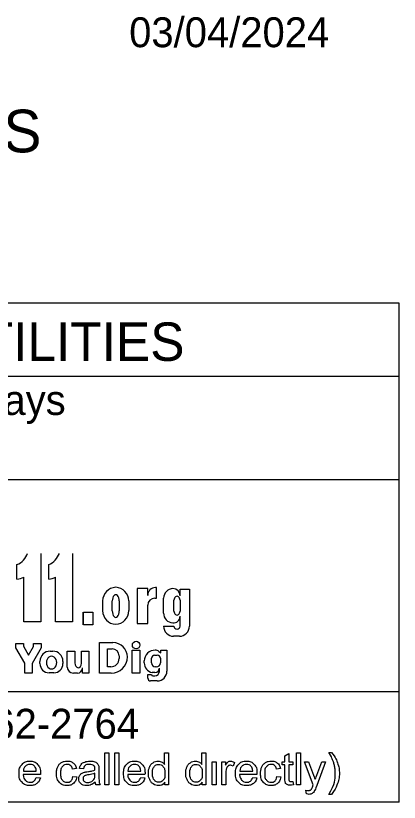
# Model space of a CAD drawing. Extents: x -3.3 to 34, y 0 to 56.8.
# Drawn here: x 4.831 to 6.628, y 1.905 to 5.59 of the extents above; entities that cross this region are included whole.
import ezdxf

# ---------------------------------------------------------------- set-up
doc = ezdxf.new("R2010")
doc.units = 0
doc.layers.add('SH_Data', color=7, linetype='Continuous')
doc.layers.add('SH_Major_Grid_Line', color=7, linetype='Continuous')

msp = doc.modelspace()

# ---------------------------------------------------------------- linework, layer by layer
at = {"layer": 'SH_Data'}
for p, q in [((6.6275, 4.2428), (2.3775, 4.2428)), ((6.6275, 1.9053), (6.6275, 4.2428)), ((2.3775, 3.9012), (6.6275, 3.9012)), ((2.3775, 3.4178), (6.6275, 3.4178)), ((6.6275, 2.4232), (2.3775, 2.4232)), ((6.6275, 1.9053), (2.3775, 1.9053))]:
    msp.add_line(p, q, dxfattribs=at)
at = {"layer": 'SH_Major_Grid_Line'}
for p, q in [((4.9487, 3.0712), (4.9487, 2.7512)), ((5.0975, 3.0712), (5.0975, 2.7512)), ((4.8371, 2.9505), (4.8371, 3.0187)), ((4.9859, 2.9505), (4.9859, 3.0187)), ((4.8694, 2.7512), (4.8694, 2.9598)), ((5.0182, 2.7512), (5.0182, 2.9598)), ((5.49, 2.9112), (5.486, 2.9112)), ((5.49, 2.8614), (5.49, 2.9112)), ((5.4493, 2.9061), (5.4005, 2.9061)), ((5.4005, 2.9061), (5.4005, 2.7431)), ((5.4493, 2.8745), (5.4493, 2.9061)), ((5.6009, 2.8719), (5.6009, 2.9029)), ((5.6009, 2.9029), (5.6444, 2.9029)), ((5.6444, 2.9029), (5.6444, 2.73)), ((5.2385, 2.8029), (5.2385, 2.8483)), ((5.2835, 2.8021), (5.2835, 2.8483)), ((5.3157, 2.8483), (5.3157, 2.8021)), ((5.3606, 2.8483), (5.3606, 2.8029)), ((5.4823, 2.8614), (5.49, 2.8614)), ((5.5239, 2.7915), (5.5239, 2.8611)), ((5.5723, 2.8008), (5.5723, 2.8518)), ((5.6009, 2.8518), (5.6009, 2.8008)), ((5.4493, 2.7431), (5.4493, 2.8284)), ((5.1456, 2.7962), (5.1456, 2.7362)), ((5.6009, 2.73), (5.6009, 2.7764)), ((4.9487, 2.7512), (4.8694, 2.7512)), ((5.0975, 2.7512), (5.0182, 2.7512)), ((5.4005, 2.7431), (5.4493, 2.7431)), ((5.5239, 2.73), (5.5723, 2.73)), ((5.2243, 2.6531), (5.2866, 2.6531)), ((5.2243, 2.5103), (5.2243, 2.6531)), ((5.5977, 2.6833), (5.5707, 2.6833)), ((4.8319, 2.6495), (4.8677, 2.6495)), ((4.8319, 2.628), (4.8319, 2.6495)), ((4.8732, 2.5571), (4.8319, 2.628)), ((4.8677, 2.6495), (4.8677, 2.6359)), ((4.8677, 2.6359), (4.8918, 2.5945)), ((4.8918, 2.5945), (4.9151, 2.6344)), ((4.9509, 2.628), (4.9088, 2.5557)), ((4.9151, 2.6344), (4.9151, 2.6495)), ((4.9151, 2.6495), (4.9509, 2.6495)), ((4.9509, 2.6495), (4.9509, 2.628)), ((5.2603, 2.5398), (5.2603, 2.6238)), ((5.2603, 2.6238), (5.2828, 2.6238)), ((5.377, 2.6174), (5.4126, 2.6174)), ((5.377, 2.5103), (5.377, 2.6174)), ((5.4126, 2.6174), (5.4126, 2.5103)), ((5.5107, 2.6178), (5.5395, 2.6178)), ((5.5107, 2.6052), (5.5107, 2.6178)), ((5.5107, 2.6178), (5.5395, 2.6178)), ((5.5395, 2.6178), (5.5395, 2.5192)), ((4.9925, 2.6133), (5.0047, 2.6133)), ((5.0727, 2.6133), (5.1075, 2.6133)), ((5.0727, 2.5387), (5.0727, 2.6133)), ((5.1075, 2.6133), (5.1075, 2.5579)), ((5.1388, 2.5563), (5.1388, 2.6133)), ((5.1388, 2.6133), (5.1736, 2.6133)), ((5.1736, 2.6133), (5.1736, 2.5103)), ((5.3154, 2.5911), (5.3154, 2.5793)), ((5.467, 2.5586), (5.467, 2.5798)), ((5.4816, 2.5944), (5.4944, 2.5944)), ((5.5021, 2.6118), (5.5107, 2.6052)), ((5.509, 2.5798), (5.509, 2.5586)), ((4.8732, 2.5103), (4.8732, 2.5571)), ((4.9088, 2.5557), (4.9088, 2.5103)), ((4.9447, 2.5547), (4.9447, 2.5654)), ((5.0525, 2.5654), (5.0525, 2.5547)), ((5.4335, 2.5578), (5.4335, 2.5679)), ((4.9088, 2.5103), (4.8732, 2.5103)), ((5.0097, 2.5119), (4.9875, 2.5119)), ((5.1199, 2.5103), (5.1011, 2.5103)), ((5.1439, 2.5103), (5.1439, 2.5344)), ((5.1736, 2.5103), (5.1439, 2.5103)), ((5.2779, 2.5103), (5.2243, 2.5103)), ((5.2759, 2.5398), (5.2603, 2.5398)), ((5.4126, 2.5103), (5.377, 2.5103)), ((5.4835, 2.5131), (5.4698, 2.5131)), ((5.4897, 2.5393), (5.4863, 2.5393)), ((5.5039, 2.5182), (5.5039, 2.5336)), ((5.45, 2.487), (5.45, 2.504)), ((5.45, 2.504), (5.467, 2.504)), ((5.4942, 2.4739), (5.4631, 2.4739)), ((5.4738, 2.497), (5.4827, 2.497))]:
    msp.add_line(p, q, dxfattribs=at)
msp.add_lwpolyline([(5.148, 2.7962), (5.1921, 2.7962), (5.1921, 2.7362), (5.148, 2.7362)], close=True, dxfattribs=at)
for points in [[(6.2974, 2.1391), (6.3105, 2.1391)], [(5.2491, 1.9864), (5.2491, 2.1366), (5.2675, 2.1366), (5.2675, 1.9864), (5.2491, 1.9864)], [(5.2956, 1.9864), (5.2956, 2.1366), (5.3141, 2.1366), (5.3141, 1.9864), (5.2956, 1.9864)], [(5.5285, 2.0827), (5.5285, 2.1366), (5.5469, 2.1366), (5.5469, 1.9864), (5.5299, 1.9864)], [(5.7034, 2.0827), (5.7034, 2.1366), (5.7218, 2.1366), (5.7218, 1.9864), (5.7048, 1.9864)], [(6.092, 2.0183), (6.092, 2.081), (6.0784, 2.081), (6.0784, 2.0953), (6.092, 2.0953), (6.092, 2.1222), (6.1105, 2.1333), (6.1105, 2.0953), (6.1289, 2.0953), (6.1289, 2.081), (6.1105, 2.081), (6.1105, 2.0172)], [(6.1465, 1.9864), (6.1465, 2.1366), (6.1649, 2.1366), (6.1649, 1.9864), (6.1465, 1.9864)], [(5.1479, 2.0617), (5.1298, 2.0641)], [(5.7509, 1.9864), (5.7509, 2.0953), (5.7693, 2.0953), (5.7693, 1.9864), (5.7509, 1.9864)], [(5.7971, 1.9864), (5.7971, 2.0953), (5.8137, 2.0953), (5.8137, 2.0788)], [(5.8562, 2.0918), (5.8497, 2.0747)], [(6.2243, 1.9863), (6.183, 2.0953), (6.2029, 2.0953), (6.2255, 2.0324)], [(6.241, 2.0318), (6.2643, 2.0953), (6.2827, 2.0953), (6.2414, 1.9845)], [(4.947, 2.0361), (4.8659, 2.0361)], [(4.8669, 2.0512), (4.9277, 2.0512)], [(5.1154, 2.0632), (5.0974, 2.0605)], [(5.2023, 2.0343), (5.2024, 2.041)], [(5.2209, 2.0566), (5.2209, 2.032)], [(5.4366, 2.0361), (5.3555, 2.0361)], [(5.3565, 2.0512), (5.4173, 2.0512)], [(5.8155, 2.0434), (5.8155, 1.9864), (5.7971, 1.9864)], [(5.9611, 2.0361), (5.88, 2.0361)], [(5.881, 2.0512), (5.9418, 2.0512)], [(6.0712, 2.0632), (6.0532, 2.0605)], [(4.9275, 2.0216), (4.9465, 2.0192)], [(5.099, 2.0263), (5.1171, 2.0238)], [(5.4171, 2.0216), (5.4361, 2.0192)], [(5.5299, 1.9864), (5.5299, 2.0001)], [(5.7048, 1.9864), (5.7048, 2.0001)], [(5.9416, 2.0216), (5.9606, 2.0192)], [(6.0548, 2.0263), (6.0729, 2.0238)], [(6.1289, 2.0029), (6.1315, 1.9866)], [(5.2267, 1.9864), (5.2075, 1.9864)], [(6.1928, 1.9446), (6.1907, 1.962)], [(6.3105, 1.9422), (6.2974, 1.9422)]]:
    msp.add_lwpolyline(points, dxfattribs=at)
msp.add_circle((5.3952, 2.6418), 0.0177, dxfattribs=at)
for centre, radius, start, end in [((4.8031, 3.1004), 0.0885, 292.5572, 340.7355), ((4.952, 3.1004), 0.0885, 292.5572, 340.7355), ((4.8291, 3.0386), 0.0885, 275.1733, 297.0931), ((4.9779, 3.0386), 0.0885, 275.1733, 297.0931), ((5.3024, 2.8483), 0.064, 92.5886, 180), ((5.2967, 2.8483), 0.064, 0, 87.4114), ((5.486, 2.8745), 0.0367, 90, 180), ((5.5698, 2.8611), 0.0459, 92.6865, 180), ((5.5658, 2.8719), 0.0351, 0, 86.9262), ((5.4823, 2.8284), 0.033, 90, 180), ((5.3024, 2.8029), 0.064, 180, 267.4114), ((5.2967, 2.8029), 0.064, 272.5886, 0), ((5.5702, 2.7915), 0.0463, 180, 265.7132), ((5.5696, 2.7764), 0.0313, 264.7825, 0), ((5.5707, 2.73), 0.0468, 180, 270), ((5.5977, 2.73), 0.0468, 270, 0), ((5.2866, 2.5848), 0.0682, 0.9944, 90), ((5.2828, 2.5911), 0.0327, 0, 90), ((5.4834, 2.5679), 0.0499, 89.0934, 180), ((5.4848, 2.5895), 0.0283, 52.1415, 91.2046), ((4.9925, 2.5654), 0.0478, 90, 180), ((5.0047, 2.5654), 0.0478, 0, 90), ((5.2779, 2.5873), 0.0769, 270, 359.0635), ((5.4816, 2.5798), 0.0146, 90, 180), ((5.4944, 2.5798), 0.0146, 0, 90), ((4.9875, 2.5547), 0.0428, 180, 270), ((5.0097, 2.5547), 0.0428, 270, 0), ((5.2759, 2.5793), 0.0395, 270, 0), ((5.4791, 2.5578), 0.0457, 180, 258.2203), ((5.4863, 2.5586), 0.0193, 180, 270), ((5.4897, 2.5586), 0.0193, 270, 0), ((5.1011, 2.5387), 0.0284, 180, 270), ((5.1199, 2.5344), 0.024, 270, 0), ((5.4827, 2.5182), 0.0212, 270, 0), ((5.4835, 2.5335), 0.0203, 270, 0), ((5.4942, 2.5192), 0.0453, 270, 0), ((5.4631, 2.487), 0.0131, 180, 270), ((5.4738, 2.5038), 0.00682, 180, 270)]:
    msp.add_arc(centre, radius, start, end, dxfattribs=at)
for centre, major_axis, ratio, start_param, end_param in [((5.2996, 2.8483), (0, 0.0291), 0.553236, 4.712389, 7.853982), ((5.5866, 2.8518), (0, 0.0184), 0.777179, 4.712389, 7.853982), ((5.2996, 2.8021), (0, 0.0308), 0.522014, 1.570796, 4.712389), ((5.5866, 2.8008), (0, 0.0184), 0.777179, 1.570796, 4.712389), ((5.5866, 2.73), (0.0143, 0), 0.959012, 3.141593, 6.283185), ((4.9991, 2.5601), (0, 0.029), 0.832186, 4.712389, 7.853982), ((4.9991, 2.5601), (0, 0.0302), 0.797287, 1.570796, 4.712389), ((5.1231, 2.5587), (-0.0011, 0.0231), 0.679042, 1.570796, 4.575961)]:
    msp.add_ellipse(centre, major_axis=major_axis, ratio=ratio, start_param=start_param, end_param=end_param, dxfattribs=at)
for points, degree in [([(6.2974, 1.9422), (6.3279, 1.9914), (6.3279, 2.0407), (6.3279, 2.0599), (6.3235, 2.0789), (6.32, 2.0942), (6.3138, 2.1084), (6.3098, 2.1176), (6.2974, 2.1391)], 3), ([(6.3105, 2.1391), (6.3298, 2.1134), (6.339, 2.0875), (6.3469, 2.0651), (6.3469, 2.0408), (6.3469, 2.0131), (6.3363, 1.9873), (6.3257, 1.9615), (6.3105, 1.9422)], 3), ([(4.9465, 2.0192), (4.942, 2.0025), (4.9298, 1.9932), (4.9177, 1.984), (4.8987, 1.984), (4.8749, 1.984), (4.8609, 1.9987), (4.8469, 2.0134), (4.8469, 2.0399), (4.8469, 2.0674), (4.861, 2.0825), (4.8752, 2.0977), (4.8977, 2.0977), (4.9195, 2.0977), (4.9333, 2.0828), (4.9471, 2.068), (4.9471, 2.041), (4.9471, 2.0394), (4.947, 2.0361)], 3), ([(4.9277, 2.0512), (4.9265, 2.065), (4.9207, 2.0719), (4.9119, 2.0826), (4.8979, 2.0826), (4.8852, 2.0826), (4.8765, 2.074), (4.8678, 2.0655), (4.8669, 2.0512)], 3), ([(5.1171, 2.0238), (5.1141, 2.0052), (5.1019, 1.9946), (5.0896, 1.984), (5.0718, 1.984), (5.0495, 1.984), (5.0359, 1.9986), (5.0223, 2.0132), (5.0223, 2.0404), (5.0223, 2.058), (5.0282, 2.0712), (5.034, 2.0845), (5.046, 2.0911), (5.0579, 2.0977), (5.0719, 2.0977), (5.0897, 2.0977), (5.1009, 2.0887), (5.1122, 2.0797), (5.1154, 2.0632)], 3), ([(5.0974, 2.0605), (5.0949, 2.0715), (5.0884, 2.077), (5.0819, 2.0826), (5.0726, 2.0826), (5.0587, 2.0826), (5.05, 2.0726), (5.0413, 2.0626), (5.0413, 2.0409), (5.0413, 2.019), (5.0497, 2.0091), (5.0581, 1.9991), (5.0717, 1.9991), (5.0825, 1.9991), (5.0898, 2.0058), (5.0971, 2.0124), (5.099, 2.0263)], 3), ([(5.2038, 1.9998), (5.1936, 1.9912), (5.1841, 1.9876), (5.1746, 1.984), (5.1638, 1.984), (5.1458, 1.984), (5.1362, 1.9928), (5.1266, 2.0015), (5.1266, 2.0151), (5.1266, 2.0231), (5.1302, 2.0297), (5.1339, 2.0363), (5.1398, 2.0403), (5.1456, 2.0443), (5.153, 2.0463), (5.1584, 2.0478), (5.1694, 2.0491), (5.1917, 2.0518), (5.2023, 2.0554), (5.2024, 2.0592), (5.2024, 2.0603), (5.2024, 2.0716), (5.1971, 2.0762), (5.1901, 2.0824), (5.1762, 2.0824), (5.1632, 2.0824), (5.157, 2.0779), (5.1508, 2.0733), (5.1479, 2.0617)], 3), ([(5.1298, 2.0641), (5.1323, 2.0757), (5.1379, 2.0828), (5.1435, 2.09), (5.1542, 2.0938), (5.1648, 2.0977), (5.1788, 2.0977), (5.1928, 2.0977), (5.2015, 2.0944), (5.2102, 2.0911), (5.2142, 2.0861), (5.2183, 2.0812), (5.22, 2.0736), (5.2209, 2.0689), (5.2209, 2.0566)], 3), ([(5.4361, 2.0192), (5.4316, 2.0025), (5.4194, 1.9932), (5.4072, 1.984), (5.3883, 1.984), (5.3644, 1.984), (5.3505, 1.9987), (5.3365, 2.0134), (5.3365, 2.0399), (5.3365, 2.0674), (5.3506, 2.0825), (5.3648, 2.0977), (5.3873, 2.0977), (5.4091, 2.0977), (5.4229, 2.0828), (5.4367, 2.068), (5.4367, 2.041), (5.4367, 2.0394), (5.4366, 2.0361)], 3), ([(5.4173, 2.0512), (5.4161, 2.065), (5.4103, 2.0719), (5.4015, 2.0826), (5.3875, 2.0826), (5.3748, 2.0826), (5.3661, 2.074), (5.3574, 2.0655), (5.3565, 2.0512)], 3), ([(5.5299, 2.0001), (5.5195, 1.984), (5.4995, 1.984), (5.4865, 1.984), (5.4755, 1.9912), (5.4646, 1.9984), (5.4586, 2.0112), (5.4526, 2.0241), (5.4526, 2.0407), (5.4526, 2.057), (5.4581, 2.0703), (5.4635, 2.0835), (5.4743, 2.0906), (5.4852, 2.0977), (5.4986, 2.0977), (5.5084, 2.0977), (5.516, 2.0935), (5.5237, 2.0894), (5.5285, 2.0827)], 3), ([(5.4716, 2.0407), (5.4716, 2.0198), (5.4805, 2.0095), (5.4893, 1.9991), (5.5012, 1.9991), (5.5133, 1.9991), (5.5218, 2.009), (5.5302, 2.0189), (5.5302, 2.0392), (5.5302, 2.0615), (5.5216, 2.072), (5.513, 2.0824), (5.5004, 2.0824), (5.4881, 2.0824), (5.4799, 2.0724), (5.4716, 2.0624), (5.4716, 2.0407)], 3), ([(5.7048, 2.0001), (5.6944, 1.984), (5.6743, 1.984), (5.6613, 1.984), (5.6504, 1.9912), (5.6395, 1.9984), (5.6335, 2.0112), (5.6275, 2.0241), (5.6275, 2.0407), (5.6275, 2.057), (5.6329, 2.0703), (5.6384, 2.0835), (5.6492, 2.0906), (5.66, 2.0977), (5.6734, 2.0977), (5.6832, 2.0977), (5.6909, 2.0935), (5.6986, 2.0894), (5.7034, 2.0827)], 3), ([(5.6465, 2.0407), (5.6465, 2.0198), (5.6553, 2.0095), (5.6641, 1.9991), (5.6761, 1.9991), (5.6882, 1.9991), (5.6967, 2.009), (5.7051, 2.0189), (5.7051, 2.0392), (5.7051, 2.0615), (5.6965, 2.072), (5.6879, 2.0824), (5.6753, 2.0824), (5.663, 2.0824), (5.6548, 2.0724), (5.6465, 2.0624), (5.6465, 2.0407)], 3), ([(5.8137, 2.0788), (5.8201, 2.0903), (5.8254, 2.094), (5.8308, 2.0977), (5.8372, 2.0977), (5.8466, 2.0977), (5.8562, 2.0918)], 3), ([(5.8497, 2.0747), (5.843, 2.0787), (5.8363, 2.0787), (5.8302, 2.0787), (5.8255, 2.075), (5.8207, 2.0714), (5.8186, 2.0649), (5.8155, 2.0551), (5.8155, 2.0434)], 3), ([(5.9606, 2.0192), (5.9561, 2.0025), (5.9439, 1.9932), (5.9317, 1.984), (5.9128, 1.984), (5.8889, 1.984), (5.875, 1.9987), (5.861, 2.0134), (5.861, 2.0399), (5.861, 2.0674), (5.8751, 2.0825), (5.8892, 2.0977), (5.9118, 2.0977), (5.9336, 2.0977), (5.9474, 2.0828), (5.9612, 2.068), (5.9612, 2.041), (5.9612, 2.0394), (5.9611, 2.0361)], 3), ([(5.9418, 2.0512), (5.9405, 2.065), (5.9348, 2.0719), (5.926, 2.0826), (5.912, 2.0826), (5.8993, 2.0826), (5.8906, 2.074), (5.8819, 2.0655), (5.881, 2.0512)], 3), ([(6.0729, 2.0238), (6.07, 2.0052), (6.0577, 1.9946), (6.0455, 1.984), (6.0277, 1.984), (6.0053, 1.984), (5.9917, 1.9986), (5.9782, 2.0132), (5.9782, 2.0404), (5.9782, 2.058), (5.984, 2.0712), (5.9899, 2.0845), (6.0018, 2.0911), (6.0137, 2.0977), (6.0278, 2.0977), (6.0455, 2.0977), (6.0568, 2.0887), (6.068, 2.0797), (6.0712, 2.0632)], 3), ([(6.0532, 2.0605), (6.0507, 2.0715), (6.0442, 2.077), (6.0377, 2.0826), (6.0285, 2.0826), (6.0146, 2.0826), (6.0059, 2.0726), (5.9972, 2.0626), (5.9972, 2.0409), (5.9972, 2.019), (6.0056, 2.0091), (6.014, 1.9991), (6.0275, 1.9991), (6.0384, 1.9991), (6.0456, 2.0058), (6.0529, 2.0124), (6.0548, 2.0263)], 3), ([(4.8659, 2.0361), (4.8669, 2.0182), (4.876, 2.0087), (4.8852, 1.9991), (4.8988, 1.9991), (4.9089, 1.9991), (4.9161, 2.0045), (4.9233, 2.0098), (4.9275, 2.0216)], 3), ([(5.2024, 2.041), (5.1923, 2.0369), (5.1722, 2.0341), (5.1608, 2.0324), (5.1561, 2.0304), (5.1514, 2.0283), (5.1488, 2.0244), (5.1463, 2.0204), (5.1463, 2.0156), (5.1463, 2.0083), (5.1519, 2.0034), (5.1574, 1.9984), (5.1682, 1.9984), (5.1788, 1.9984), (5.1871, 2.0031), (5.1954, 2.0078), (5.1993, 2.0158), (5.2023, 2.0221), (5.2023, 2.0343)], 3), ([(5.2209, 2.032), (5.2209, 2.0063), (5.2221, 1.9995), (5.2233, 1.9927), (5.2267, 1.9864)], 3), ([(5.3555, 2.0361), (5.3565, 2.0182), (5.3656, 2.0087), (5.3748, 1.9991), (5.3884, 1.9991), (5.3985, 1.9991), (5.4057, 2.0045), (5.4129, 2.0098), (5.4171, 2.0216)], 3), ([(5.88, 2.0361), (5.881, 2.0182), (5.8901, 2.0087), (5.8992, 1.9991), (5.9129, 1.9991), (5.923, 1.9991), (5.9302, 2.0045), (5.9374, 2.0098), (5.9416, 2.0216)], 3), ([(6.2255, 2.0324), (6.2299, 2.0205), (6.2334, 2.0073), (6.2366, 2.0197), (6.241, 2.0318)], 3), ([(5.2075, 1.9864), (5.2047, 1.9921), (5.2038, 1.9998)], 2), ([(6.1315, 1.9866), (6.1238, 1.9849), (6.1176, 1.9849), (6.1076, 1.9849), (6.1021, 1.9881), (6.0965, 1.9913), (6.0943, 1.9965), (6.092, 2.0017), (6.092, 2.0183)], 3), ([(6.1105, 2.0172), (6.1105, 2.0093), (6.1114, 2.007), (6.1124, 2.0048), (6.1146, 2.0034), (6.1168, 2.0021), (6.1209, 2.0021), (6.1239, 2.0021), (6.1289, 2.0029)], 3), ([(6.1907, 1.962), (6.1967, 1.9603), (6.2012, 1.9603), (6.2074, 1.9603), (6.211, 1.9624), (6.2147, 1.9644), (6.2171, 1.9681), (6.2188, 1.9709), (6.2227, 1.9818), (6.2232, 1.9834), (6.2243, 1.9863)], 3), ([(6.2414, 1.9845), (6.2348, 1.9667), (6.2311, 1.9599), (6.2262, 1.9508), (6.2198, 1.9466), (6.2135, 1.9424), (6.2046, 1.9424), (6.1993, 1.9424), (6.1928, 1.9446)], 3)]:
    msp.add_open_spline(points, degree=degree, dxfattribs=at)

# ---------------------------------------------------------------- texts
for s, height, p in [('03/04/2024', 0.14, (5.3625, 5.4425)), ('ADA DESIGN WAIVERS', 0.2, (1.9944, 4.9499)), ('UNDERGROUND UTILITIES', 0.18, (2.5057, 3.9731)), ('Contact Two Working Days', 0.14, (2.7972, 3.7196)), ('OHIO811, 8-1-1, or 1-800-362-2764', 0.14, (2.422, 2.2031))]:
    msp.add_text(s, height=height, dxfattribs=at).set_placement(p)

doc.saveas('drawing.dxf')
